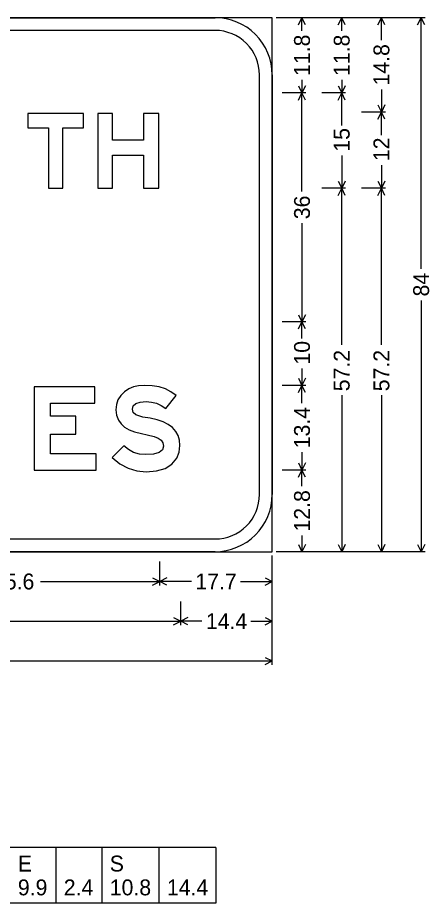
# Model space of a CAD drawing. Extents: x 1820207 to 1820557, y 740216 to 740315.
# Drawn here: x 1820496.52 to 1820499.22, y 740224.44 to 740230.24 of the extents above; entities that cross this region are included whole.
import ezdxf

# ---------------------------------------------------------------- set-up
doc = ezdxf.new("R2010")
doc.units = 0
doc.layers.add('SC_Scratch3', color=7, linetype='Continuous')

msp = doc.modelspace()

# ---------------------------------------------------------------- linework, layer by layer
at = {"layer": 'SC_Scratch3'}
for p, q in [((1820499.1935, 740230.2431), (1820498.217, 740230.2431)), ((1820498.4123, 740230.2431), (1820498.256, 740230.2431)), ((1820498.363, 740230.1965), (1820498.3863, 740230.2431)), ((1820498.3863, 740230.1578), (1820498.3863, 740230.2431)), ((1820498.4096, 740230.1965), (1820498.3863, 740230.2431)), ((1820498.6727, 740230.2431), (1820498.5165, 740230.2431)), ((1820498.6234, 740230.1965), (1820498.6467, 740230.2431)), ((1820498.6467, 740230.1578), (1820498.6467, 740230.2431)), ((1820498.67, 740230.1965), (1820498.6467, 740230.2431)), ((1820498.9331, 740230.2431), (1820498.7769, 740230.2431)), ((1820498.8838, 740230.1965), (1820498.9071, 740230.2431)), ((1820498.9071, 740230.0953), (1820498.9071, 740230.2431)), ((1820498.9304, 740230.1965), (1820498.9071, 740230.2431)), ((1820499.1442, 740230.1965), (1820499.1675, 740230.2431)), ((1820499.1675, 740228.5963), (1820499.1675, 740230.2431)), ((1820499.1908, 740230.1965), (1820499.1675, 740230.2431)), ((1820498.363, 740229.7966), (1820498.3863, 740229.75)), ((1820498.3863, 740229.8352), (1820498.3863, 740229.75)), ((1820498.4096, 740229.7966), (1820498.3863, 740229.75)), ((1820498.6234, 740229.7966), (1820498.6467, 740229.75)), ((1820498.6467, 740229.8352), (1820498.6467, 740229.75)), ((1820498.67, 740229.7966), (1820498.6467, 740229.75)), ((1820498.4123, 740229.75), (1820498.256, 740229.75)), ((1820498.363, 740229.7034), (1820498.3863, 740229.75)), ((1820498.3863, 740229.1038), (1820498.3863, 740229.75)), ((1820498.4096, 740229.7034), (1820498.3863, 740229.75)), ((1820498.6727, 740229.75), (1820498.5165, 740229.75)), ((1820498.6234, 740229.7034), (1820498.6467, 740229.75)), ((1820498.6467, 740229.5361), (1820498.6467, 740229.75)), ((1820498.67, 740229.7034), (1820498.6467, 740229.75)), ((1820498.9071, 740229.7727), (1820498.9071, 740229.625)), ((1820498.9331, 740229.625), (1820498.7769, 740229.625)), ((1820498.8838, 740229.6716), (1820498.9071, 740229.625)), ((1820498.8838, 740229.5784), (1820498.9071, 740229.625)), ((1820498.9304, 740229.6716), (1820498.9071, 740229.625)), ((1820498.9071, 740229.473), (1820498.9071, 740229.625)), ((1820498.9304, 740229.5784), (1820498.9071, 740229.625)), ((1820498.6467, 740229.3389), (1820498.6467, 740229.125)), ((1820498.9071, 740229.277), (1820498.9071, 740229.125)), ((1820498.6234, 740229.1716), (1820498.6467, 740229.125)), ((1820498.67, 740229.1716), (1820498.6467, 740229.125)), ((1820498.8838, 740229.1716), (1820498.9071, 740229.125)), ((1820498.9304, 740229.1716), (1820498.9071, 740229.125)), ((1820498.6727, 740229.125), (1820498.5165, 740229.125)), ((1820498.6727, 740229.125), (1820498.5165, 740229.125)), ((1820498.6234, 740229.0784), (1820498.6467, 740229.125)), ((1820498.6467, 740228.0997), (1820498.6467, 740229.125)), ((1820498.67, 740229.0784), (1820498.6467, 740229.125)), ((1820498.9331, 740229.125), (1820498.7769, 740229.125)), ((1820498.9331, 740229.125), (1820498.7769, 740229.125)), ((1820498.8838, 740229.0784), (1820498.9071, 740229.125)), ((1820498.9071, 740228.0997), (1820498.9071, 740229.125)), ((1820498.9304, 740229.0784), (1820498.9071, 740229.125)), ((1820498.3863, 740228.8962), (1820498.3863, 740228.25)), ((1820499.1675, 740228.3899), (1820499.1675, 740226.7431)), ((1820498.363, 740228.2966), (1820498.3863, 740228.25)), ((1820498.4096, 740228.2966), (1820498.3863, 740228.25)), ((1820498.4123, 740228.25), (1820498.256, 740228.25)), ((1820498.363, 740228.2034), (1820498.3863, 740228.25)), ((1820498.3863, 740228.14), (1820498.3863, 740228.25)), ((1820498.4096, 740228.2034), (1820498.3863, 740228.25)), ((1820498.3863, 740227.9434), (1820498.3863, 740227.8334)), ((1820498.363, 740227.8799), (1820498.3863, 740227.8334)), ((1820498.4096, 740227.8799), (1820498.3863, 740227.8334)), ((1820498.4123, 740227.8334), (1820498.256, 740227.8334)), ((1820498.363, 740227.7868), (1820498.3863, 740227.8334)), ((1820498.3863, 740227.7163), (1820498.3863, 740227.8334)), ((1820498.4096, 740227.7868), (1820498.3863, 740227.8334)), ((1820498.6467, 740227.7684), (1820498.6467, 740226.7431)), ((1820498.9071, 740227.7684), (1820498.9071, 740226.7431)), ((1820498.3863, 740227.3948), (1820498.3863, 740227.2778)), ((1820498.363, 740227.3244), (1820498.3863, 740227.2778)), ((1820498.4096, 740227.3244), (1820498.3863, 740227.2778)), ((1820498.4123, 740227.2778), (1820498.256, 740227.2778)), ((1820498.4123, 740227.2778), (1820498.256, 740227.2778)), ((1820498.363, 740227.2312), (1820498.3863, 740227.2778)), ((1820498.3863, 740227.1717), (1820498.3863, 740227.2778)), ((1820498.4096, 740227.2312), (1820498.3863, 740227.2778)), ((1820498.3863, 740226.8492), (1820498.3863, 740226.7431)), ((1820498.363, 740226.7897), (1820498.3863, 740226.7431)), ((1820498.4096, 740226.7897), (1820498.3863, 740226.7431)), ((1820498.6234, 740226.7897), (1820498.6467, 740226.7431)), ((1820498.67, 740226.7897), (1820498.6467, 740226.7431)), ((1820498.8838, 740226.7897), (1820498.9071, 740226.7431)), ((1820498.9304, 740226.7897), (1820498.9071, 740226.7431)), ((1820499.1442, 740226.7897), (1820499.1675, 740226.7431)), ((1820499.1908, 740226.7897), (1820499.1675, 740226.7431)), ((1820498.191, 740226.0009), (1820498.191, 740226.717)), ((1820499.1935, 740226.7431), (1820498.217, 740226.7431)), ((1820498.4123, 740226.7431), (1820498.256, 740226.7431)), ((1820498.6727, 740226.7431), (1820498.5165, 740226.7431)), ((1820498.9331, 740226.7431), (1820498.7769, 740226.7431)), ((1820497.4532, 740226.5217), (1820497.4532, 740226.678)), ((1820497.4532, 740226.5217), (1820497.4532, 740226.678)), ((1820498.191, 740226.5217), (1820498.191, 740226.678)), ((1820496.6721, 740226.5477), (1820497.4532, 740226.5477)), ((1820497.4065, 740226.5711), (1820497.4532, 740226.5477)), ((1820497.4065, 740226.5244), (1820497.4532, 740226.5477)), ((1820497.4997, 740226.5711), (1820497.4532, 740226.5477)), ((1820497.661, 740226.5477), (1820497.4532, 740226.5477)), ((1820497.4997, 740226.5244), (1820497.4532, 740226.5477)), ((1820497.9831, 740226.5477), (1820498.191, 740226.5477)), ((1820498.1444, 740226.5711), (1820498.191, 740226.5477)), ((1820498.1444, 740226.5244), (1820498.191, 740226.5477)), ((1820497.591, 740226.2613), (1820497.591, 740226.4176)), ((1820497.591, 740226.2613), (1820497.591, 740226.4176)), ((1820498.191, 740226.2613), (1820498.191, 740226.4176)), ((1820497.5444, 740226.3106), (1820497.591, 740226.2873)), ((1820497.6375, 740226.3106), (1820497.591, 740226.2873)), ((1820498.1444, 740226.3106), (1820498.191, 740226.2873)), ((1820496.4107, 740226.2873), (1820497.591, 740226.2873)), ((1820497.5444, 740226.264), (1820497.591, 740226.2873)), ((1820497.7302, 740226.2873), (1820497.591, 740226.2873)), ((1820497.6375, 740226.264), (1820497.591, 740226.2873)), ((1820498.0517, 740226.2873), (1820498.191, 740226.2873)), ((1820498.1444, 740226.264), (1820498.191, 740226.2873)), ((1820495.3307, 740226.0269), (1820498.191, 740226.0269)), ((1820498.1444, 740226.0502), (1820498.191, 740226.0269)), ((1820498.1444, 740226.0036), (1820498.191, 740226.0269)), ((1820497.822, 740224.803), (1820492.191, 740224.803)), ((1820496.7721, 740224.803), (1820496.7721, 740224.4384)), ((1820497.0737, 740224.803), (1820497.0737, 740224.4384)), ((1820497.4484, 740224.803), (1820497.4484, 740224.4384)), ((1820497.822, 740224.803), (1820497.822, 740224.4384)), ((1820497.822, 740224.4384), (1820492.191, 740224.4384))]:
    msp.add_line(p, q, dxfattribs=at)
for points in [[(1820492.191, 740226.7431), (1820498.191, 740226.7431), (1820498.191, 740230.2431), (1820492.191, 740230.2431), (1820492.191, 740226.7431), (1820492.191, 740226.7431), (1820492.191, 740226.7431)], [(1820492.566, 740230.2431), (1820497.816, 740230.2431)], [(1820497.816, 740230.1597), (1820492.566, 740230.1597)], [(1820497.816, 740230.1597), (1820497.816, 740230.1597), (1820497.816, 740230.1597)], [(1820498.1076, 740227.1181), (1820498.1076, 740229.8681)], [(1820498.191, 740229.8681), (1820498.191, 740227.1181)], [(1820498.1076, 740227.1181), (1820498.1076, 740227.1181), (1820498.1076, 740227.1181)], [(1820492.566, 740226.8264), (1820497.816, 740226.8264)], [(1820497.816, 740226.7431), (1820492.566, 740226.7431)]]:
    msp.add_lwpolyline(points, dxfattribs=at)
for points in [[(1820496.7241, 740229.125), (1820496.8191, 740229.125), (1820496.8191, 740229.521), (1820496.9541, 740229.521), (1820496.9541, 740229.6154), (1820496.5882, 740229.6154), (1820496.5882, 740229.521), (1820496.7241, 740229.521)], [(1820497.0482, 740229.125), (1820497.1443, 740229.125), (1820497.1443, 740229.3421), (1820497.3462, 740229.3421), (1820497.3462, 740229.125), (1820497.4476, 740229.125), (1820497.4476, 740229.6154), (1820497.3462, 740229.6154), (1820497.3462, 740229.4405), (1820497.1443, 740229.4405), (1820497.1443, 740229.6154), (1820497.0482, 740229.6154)], [(1820497.0365, 740227.3846), (1820496.737, 740227.3846), (1820496.737, 740227.5128), (1820496.9024, 740227.5128), (1820496.9024, 740227.6303), (1820496.737, 740227.6303), (1820496.737, 740227.7158), (1820497.0288, 740227.7158), (1820497.0288, 740227.8226), (1820496.6298, 740227.8226), (1820496.6298, 740227.2778), (1820497.0365, 740227.2778)], [(1820497.141, 740227.3599), (1820497.1925, 740227.3191), (1820497.2471, 740227.2903), (1820497.3043, 740227.2728), (1820497.3646, 740227.2671), (1820497.4329, 740227.2726), (1820497.489, 740227.2892), (1820497.5329, 740227.3171), (1820497.5646, 740227.3564), (1820497.5806, 740227.3959), (1820497.586, 740227.4386), (1820497.5828, 740227.4731), (1820497.5738, 740227.5041), (1820497.5584, 740227.5317), (1820497.5372, 740227.556), (1820497.5099, 740227.5767), (1820497.4764, 740227.5941), (1820497.4369, 740227.6079), (1820497.3915, 740227.6185), (1820497.3433, 740227.6256), (1820497.297, 740227.6395), (1820497.2796, 740227.6544), (1820497.2739, 740227.6764), (1820497.2795, 740227.6982), (1820497.2965, 740227.714), (1820497.3249, 740227.7235), (1820497.3646, 740227.7267), (1820497.3987, 740227.7238), (1820497.4318, 740227.7155), (1820497.4633, 740227.7014), (1820497.4937, 740227.682), (1820497.5607, 740227.7673), (1820497.5262, 740227.7918), (1820497.4915, 740227.8097), (1820497.4507, 740227.8228), (1820497.404, 740227.8306), (1820497.3515, 740227.8333), (1820497.315, 740227.8306), (1820497.2815, 740227.8228), (1820497.2508, 740227.8096), (1820497.2227, 740227.7912), (1820497.1977, 740227.7667), (1820497.1798, 740227.7388), (1820497.1692, 740227.7075), (1820497.1656, 740227.6727), (1820497.1698, 740227.6388), (1820497.1827, 740227.6056), (1820497.1996, 740227.5804), (1820497.2227, 740227.559), (1820497.2522, 740227.5415), (1820497.2882, 740227.528), (1820497.4162, 740227.4985), (1820497.4432, 740227.4874), (1820497.4627, 740227.4732), (1820497.4743, 740227.4559), (1820497.4783, 740227.4352), (1820497.471, 740227.4106), (1820497.4491, 740227.3933), (1820497.4127, 740227.3828), (1820497.3618, 740227.3794), (1820497.3202, 740227.3829), (1820497.2825, 740227.3939), (1820497.2482, 740227.412), (1820497.2179, 740227.4377)]]:
    msp.add_lwpolyline(points, close=True, dxfattribs=at)
for centre, radius, start, end in [((1820497.816, 740229.8681), 0.375, 0, 90.00021), ((1820497.816, 740229.8681), 0.2917, 0, 90.00021), ((1820497.816, 740227.1181), 0.375, 270.00006, 0.00027), ((1820497.816, 740227.1181), 0.2917, 270.00006, 0.00027)]:
    msp.add_arc(centre, radius, start, end, dxfattribs=at)

# ---------------------------------------------------------------- texts
for s, p in [('11.8', (1820498.4384, 740229.8613)), ('11.8', (1820498.6988, 740229.8613)), ('14.8', (1820498.9592, 740229.7988)), ('15', (1820498.6988, 740229.365)), ('12', (1820498.9592, 740229.303)), ('36', (1820498.4384, 740228.9223)), ('84', (1820499.2196, 740228.4159)), ('10', (1820498.4384, 740227.9694)), ('57.2', (1820498.6988, 740227.7944)), ('57.2', (1820498.9592, 740227.7944)), ('13.4', (1820498.4384, 740227.4209)), ('12.8', (1820498.4384, 740226.8752))]:
    msp.add_text(s, height=0.10417, rotation=90.00021, dxfattribs=at).set_placement(p)
for s, height, p in [('45.6', 0.10417, (1820496.3602, 740226.4957)), ('17.7', 0.10417, (1820497.6871, 740226.4957)), ('14.4', 0.10417, (1820497.7562, 740226.2353)), ('E', 0.1042, (1820496.5232, 740224.6467)), ('S', 0.1042, (1820497.1258, 740224.6467)), ('9.9', 0.10417, (1820496.5232, 740224.4905)), ('2.4', 0.10417, (1820496.8242, 740224.4905)), ('10.8', 0.10417, (1820497.1258, 740224.4905)), ('14.4', 0.10417, (1820497.5005, 740224.4905))]:
    msp.add_text(s, height=height, dxfattribs=at).set_placement(p)

doc.saveas('drawing.dxf')
